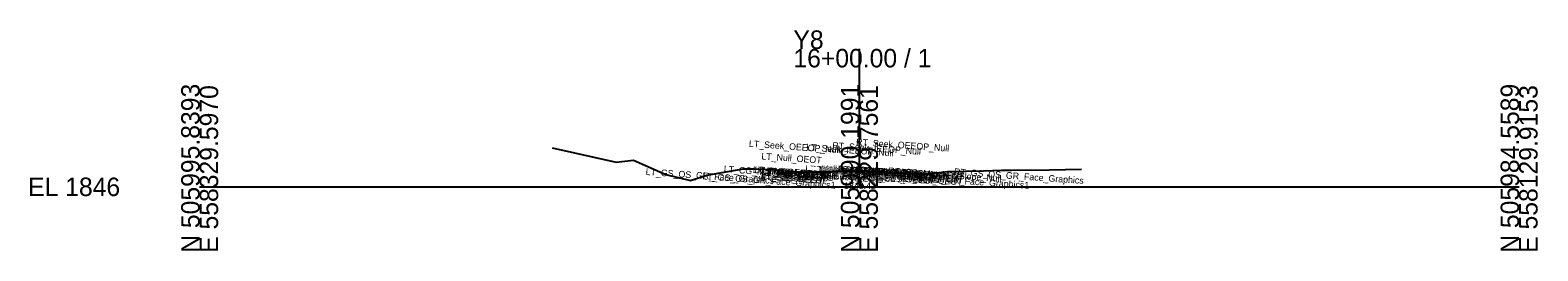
# Model space of a CAD drawing. Extents: x -26 to 203, y -10 to 8070.
# Drawn here: x -25.7 to 202.8, y 5990.3 to 6023.7 of the extents above; entities that cross this region are included whole.
import ezdxf

# ---------------------------------------------------------------- set-up
doc = ezdxf.new("R2010")
doc.units = 0
for name, color, linetype in [('Default', 7, 'Continuous'), ('Exist Cross Section Cell', 7, 'Continuous'), ('Exist XS Center Line Elevation Label', 7, 'Continuous'), ('Exist XS Ground Line', 7, 'Continuous'), ('Prop CMT Pvmt Course 1', 7, 'Continuous'), ('Prop CMT Pvmt Surface', 7, 'Continuous'), ('Prop XS Earthwork Shape', 7, 'Continuous'), ('Typical Text Grade Point CELL', 7, 'Continuous')]:
    doc.layers.add(name, color=color, linetype=linetype)

msp = doc.modelspace()

# ---------------------------------------------------------------- linework, layer by layer
at = {"layer": 'Exist Cross Section Cell'}
for p, q in [((100, 6000), (100, 6020.89)), ((0, 6000), (100, 6000)), ((100, 6000), (200, 6000))]:
    msp.add_line(p, q, dxfattribs=at)
at = {"layer": 'Exist XS Ground Line'}
for p, q in [((53.41, 6005.89), (63.15, 6003.75)), ((63.15, 6003.75), (65.76, 6004.04)), ((65.76, 6004.04), (70.64, 6001.86)), ((70.64, 6001.86), (74.42, 6000.96)), ((74.42, 6000.96), (76.87, 6001.75)), ((76.87, 6001.75), (82.37, 6002.73)), ((82.37, 6002.73), (84.08, 6002.74)), ((84.08, 6002.74), (87.31, 6002.65)), ((87.31, 6002.65), (87.92, 6002.08)), ((87.92, 6002.08), (89.48, 6002.2)), ((89.48, 6002.2), (89.84, 6002.19)), ((89.84, 6002.19), (99.03, 6002.4)), ((99.03, 6002.4), (100.12, 6002.42)), ((100.12, 6002.42), (109.46, 6002)), ((109.46, 6002), (110.42, 6001.98)), ((110.42, 6001.98), (113.38, 6002.32)), ((113.38, 6002.32), (118.83, 6002.42)), ((118.83, 6002.42), (121.55, 6002.5)), ((121.55, 6002.5), (122.46, 6002.52)), ((122.46, 6002.52), (123.07, 6002.54)), ((123.07, 6002.54), (128.8, 6002.58)), ((128.8, 6002.58), (133.69, 6002.66))]:
    msp.add_line(p, q, dxfattribs=at)
at = {"layer": 'Prop CMT Pvmt Course 1'}
for points in [[(100, 6002.42), (98, 6002.38), (97.99, 6002.38), (89.69, 6002.19), (89.68, 6002.19)], [(100, 6002.42), (102, 6002.33), (102.01, 6002.33), (105.99, 6002.16), (106, 6002.16), (110.5, 6001.96)]]:
    msp.add_lwpolyline(points, dxfattribs=at)
at = {"layer": 'Prop CMT Pvmt Surface'}
for points in [[(100, 6002.42), (98, 6002.38), (97.99, 6002.38), (89.69, 6002.19), (89.68, 6002.19), (89.68, 6002.19)], [(100, 6002.42), (102, 6002.33), (102.01, 6002.33), (105.99, 6002.16), (106, 6002.16), (110.5, 6001.96)]]:
    msp.add_lwpolyline(points, dxfattribs=at)
at = {"layer": 'Prop XS Earthwork Shape'}
msp.add_lwpolyline([(100.12, 6002.42), (102, 6002.33), (105.99, 6002.16), (109.46, 6002), (110.5, 6001.96), (110.49, 6001.83), (100, 6002.3), (89.68, 6002.07), (89.68, 6002.19), (89.84, 6002.19), (98, 6002.38), (99.03, 6002.4)], close=True, dxfattribs=at)

# ---------------------------------------------------------------- texts
at = {"layer": 'Default'}
msp.add_text('-', height=0.0001, dxfattribs=at).set_placement((0, 6000))
at = {"layer": 'Exist Cross Section Cell'}
for s, p in [('Y8', (90, 6020.89)), ('16+00.00 / 1', (90, 6018.09)), ('EL 1846', (-26, 5998.6))]:
    msp.add_text(s, height=2.8, dxfattribs=at).set_placement(p)
for s, p in [('N 505995.8393', (0, 5990)), ('E 558329.5970', (2.8, 5990)), ('N 505990.1991', (100, 5990)), ('E 558229.7561', (102.8, 5990)), ('N 505984.5589', (200, 5990)), ('E 558129.9153', (202.8, 5990))]:
    msp.add_text(s, height=2.8, rotation=90, dxfattribs=at).set_placement(p)
at = {"layer": 'Exist XS Center Line Elevation Label'}
msp.add_text('1848.42', height=1, dxfattribs=at).set_placement((97.67, 5999.67))
at = {"layer": 'Typical Text Grade Point CELL'}
for s, p in [('LT_Seek_OEEOP_Null', (83.23, 6006.06)), ('LT_Seek_IEEOP_Null', (91.93, 6005.53)), ('RT_Seek_IEEOP_Null', (95.87, 6005.78)), ('RT_Seek_OEEOP_Null', (99.49, 6006.31)), ('LT_Null_OEOT', (85.12, 6004.16)), ('LT_GS_OS_GR_Face_Graphics', (67.58, 6001.8)), ('LT_GS_OS_GR_Face_Graphics1', (76.18, 6001.14)), ('LT_CG_MatchPVSlope_Null', (79.42, 6002.21)), ('LT_PV_Sub_Tie_Out', (83.83, 6002.1)), ('LT_Null OEEOP Test', (84.08, 6002.12)), ('LT_PV2_OEEOP', (85.05, 6001.77)), ('LT_PV3_OEEOP', (85.05, 6001.52)), ('LT_Sub_OEEOP', (85.07, 6001.14)), ('LT_PV1_OEEOP', (85.17, 6001.88)), ('LT_PV2_OEOT', (85.22, 6001.74)), ('LT_PV3_OEOT', (85.22, 6001.49)), ('LT_Sub_OEOT', (85.24, 6001.11)), ('LT_PV1_OEOT', (85.34, 6001.98)), ('LT_Pvmt Out', (85.93, 6001.95)), ('LT_Null IEEOP Test', (91.78, 6002.26)), ('LT_PV_Sub_Tie_In', (92.76, 6002.24)), ('LT_PV2_IEEOP', (93.75, 6001.92)), ('LT_PV3_IEEOP', (93.75, 6001.67)), ('LT_Sub_IEEOP', (93.77, 6001.3)), ('LT_PV1_IEEOP', (93.87, 6002.04)), ('Null RT Pvmt Slope', (94.26, 6002.32)), ('Null LT Pvmt Slope', (94.32, 6002.32)), ('PV1_Overlay_Null', (94.75, 6002.16)), ('LT_Pvmt In', (94.84, 6002.1)), ('RT_PV_Sub_Tie_In', (96.7, 6002.2)), ('RT_Null IEEOP Test', (96.72, 6002.21)), ('Sub_PGL', (97.35, 6001.23)), ('PV2_PGL', (97.32, 6001.86)), ('PV3_PGL', (97.32, 6001.61)), ('PV1_PGL', (97.44, 6002.1)), ('RT_PV2_IEEOP', (97.69, 6001.88)), ('RT_PV3_IEEOP', (97.69, 6001.63)), ('RT_Sub_IEEOP', (97.71, 6001.26)), ('RT_PV1_IEEOP', (97.81, 6002)), ('RT_Pvmt In', (98.8, 6002.06)), ('CL', (99.2, 6001.91)), ('RT_Null OEEOP Test', (99.34, 6002.11)), ('RT_PV_Sub_Tie_Out', (100.09, 6002.07)), ('RT_PV2_OEEOP', (101.31, 6001.73)), ('RT_PV3_OEEOP', (101.31, 6001.48)), ('RT_Sub_OEEOP', (101.33, 6001.11)), ('RT_PV1_OEEOP', (101.43, 6001.85)), ('RT_Pvmt Out', (102.17, 6001.92)), ('RT_CG_MatchPVSlope_Null', (104.37, 6001.94)), ('RT_GS_OS_GR_Face_Graphics1', (105.32, 6001.14)), ('RT_PV2_OEOT', (106.16, 6001.51)), ('RT_PV3_OEOT', (106.16, 6001.26)), ('RT_Sub_OEOT', (106.19, 6000.88)), ('RT_PV1_OEOT', (106.28, 6001.75)), ('RT_GS_OS_GR_Face_Graphics', (114.32, 6001.81))]:
    msp.add_text(s, height=1, rotation=356, dxfattribs=at).set_placement(p)

doc.saveas('drawing.dxf')
